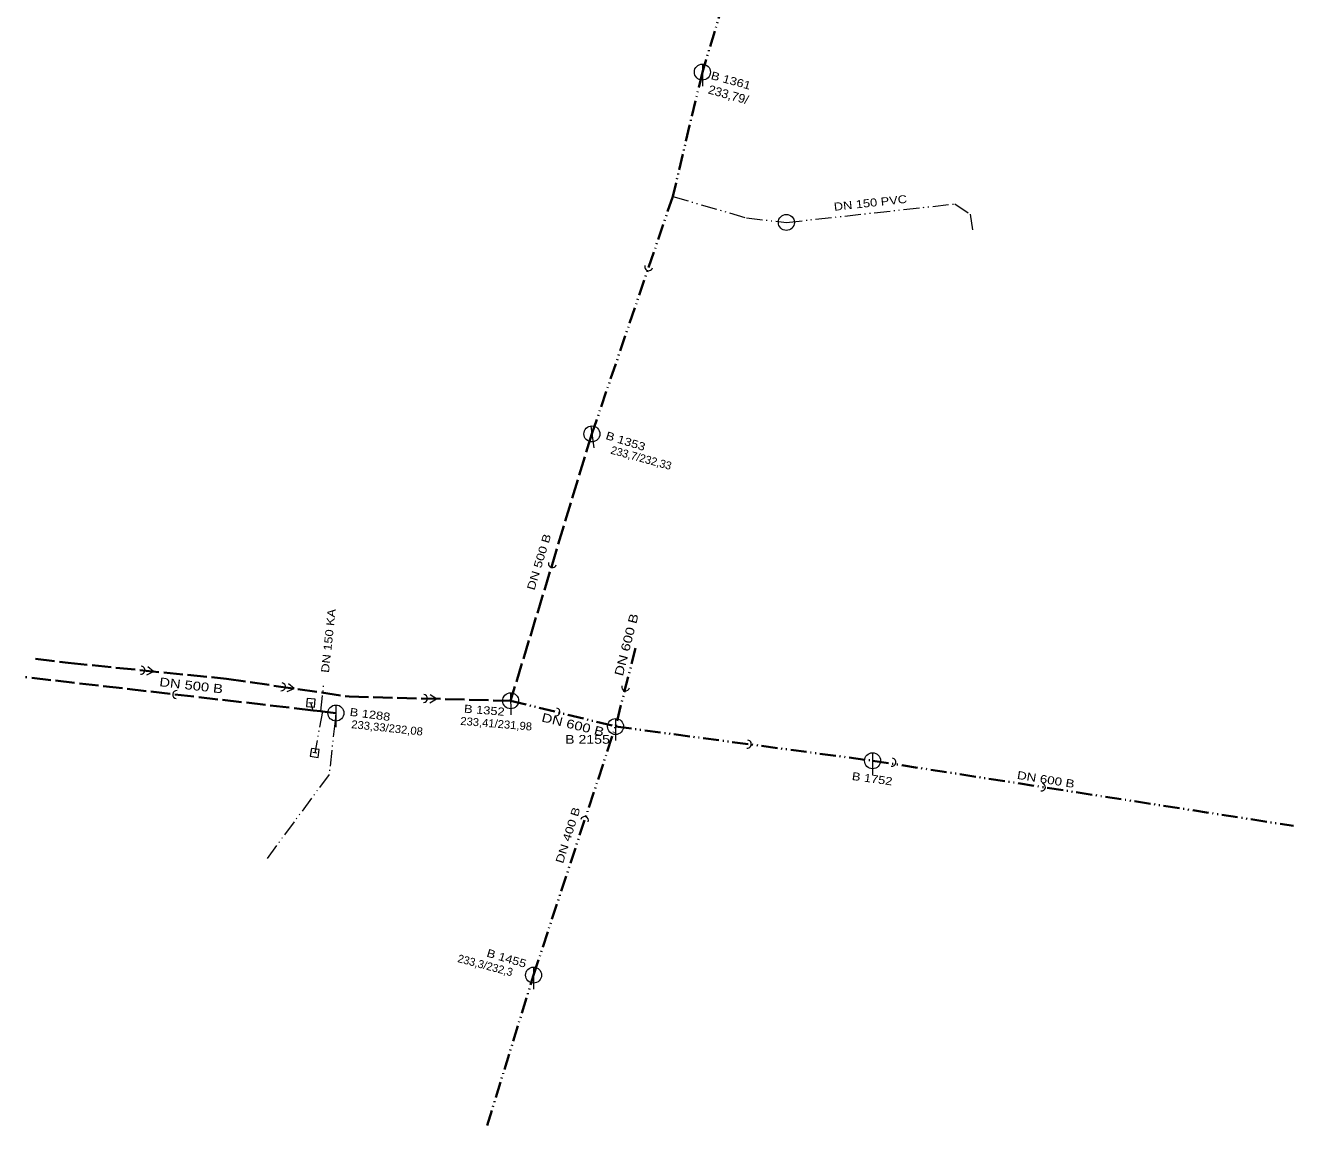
# Model space of a CAD drawing. Extents: x -645297 to -645138, y -1043752 to -1043474.
# Drawn here: x -645296.8 to -645138.3, y -1043751.8 to -1043614.2 of the extents above; entities that cross this region are included whole.
import ezdxf
from ezdxf.enums import TextEntityAlignment as Align

# ---------------------------------------------------------------- set-up
doc = ezdxf.new("R2010")
doc.units = 0
doc.header["$LTSCALE"] = 0.4
doc.linetypes.add('DASH_DOUBLE_DOT', pattern=[9.2, 5, -1.2, 0.3, -1.2, 0.3, -1.2])
doc.linetypes.add('LONG_DASHED', pattern=[7.5, 6, -1.5])
for name, color, linetype, lineweight in [('10', 7, 'Continuous', 13), ('14', 7, 'Continuous', 13), ('23', 7, 'LONG_DASHED', 35), ('24', 7, 'DASH_DOUBLE_DOT', 35), ('26', 7, 'DASH_DOUBLE_DOT', 35), ('34', 7, 'DASH_DOUBLE_DOT', 13), ('36', 7, 'DASH_DOUBLE_DOT', 13)]:
    doc.layers.add(name, color=color, linetype=linetype, lineweight=lineweight)
doc.layers.add('29', color=7, linetype='Continuous')
doc.layers.add('39', color=7, linetype='Continuous')

msp = doc.modelspace()

# ---------------------------------------------------------------- linework, layer by layer
at = {"layer": '10'}
for p, q in [((-645212.225, -1043619.066), (-645212.225, -1043621.814)), ((-645226.159, -1043664.308), (-645225.805, -1043667.033)), ((-645260.911, -1043698.942), (-645261.409, -1043698.898)), ((-645236.186, -1043697.65), (-645236.17, -1043700.398)), ((-645258.01, -1043699.18), (-645258.01, -1043701.928)), ((-645223.075, -1043700.865), (-645223.075, -1043703.613)), ((-645260.402, -1043705.192), (-645260.898, -1043705.128)), ((-645190.957, -1043705.14), (-645190.964, -1043707.888)), ((-645233.32, -1043731.94), (-645233.32, -1043734.688))]:
    msp.add_line(p, q, dxfattribs=at)
for points in [[(-645260.618, -1043698.466), (-645261.614, -1043698.378), (-645261.702, -1043699.374), (-645260.706, -1043699.462)], [(-645260.09, -1043704.729), (-645261.081, -1043704.6), (-645261.21, -1043705.591), (-645260.219, -1043705.72)]]:
    msp.add_lwpolyline(points, close=True, dxfattribs=at)
for centre, radius in [((-645212.2247, -1043620.0663), 1.0002), ((-645201.7333, -1043638.8638), 1), ((-645226.0301, -1043665.3002), 1.0002), ((-645236.1801, -1043698.6502), 1.0002), ((-645258.0097, -1043700.1803), 1.0002), ((-645223.0747, -1043701.8653), 1.0002), ((-645190.9597, -1043706.1403), 1.0002), ((-645233.3197, -1043732.9403), 1.0002)]:
    msp.add_circle(centre, radius, dxfattribs=at)
at = {"layer": '14'}
for points in [[(-645281.631, -1043695.407), (-645280.785, -1043694.99), (-645281.531, -1043694.412)], [(-645264.088, -1043697.51), (-645263.224, -1043697.13), (-645263.944, -1043696.52)], [(-645246.274, -1043698.89), (-645245.461, -1043698.411), (-645246.248, -1043697.89)]]:
    msp.add_lwpolyline(points, dxfattribs=at)
for centre, start, end in [((-645218.9241, -1043644.393), 163.02829, 343.02829), ((-645230.9599, -1043681.4969), 163.07249, 343.07249), ((-645282.3763, -1043694.8297), 264.28367, 84.28367), ((-645277.9037, -1043697.877), 83.39779, 263.39779), ((-645264.8069, -1043696.8994), 261.73408, 81.73408), ((-645221.8048, -1043696.9106), 165.61424, 345.61424), ((-645247.06, -1043698.3688), 268.52246, 88.52246), ((-645230.5152, -1043700.0405), 256.21607, 76.21607), ((-645206.6052, -1043704.0577), 262.41763, 82.41763), ((-645188.5448, -1043706.3294), 260.84248, 80.84248), ((-645169.8615, -1043709.4306), 261.13659, 81.13659), ((-645226.9519, -1043713.6266), 341.75332, 161.75332)]:
    msp.add_arc(centre, 0.5, start, end, dxfattribs=at)
at = {"layer": '23'}
for p, q in [((-645226.03, -1043665.3), (-645236.18, -1043698.65)), ((-645260.853, -1043699.851), (-645296.813, -1043695.689)), ((-645258.01, -1043700.18), (-645259.701, -1043699.984))]:
    msp.add_line(p, q, dxfattribs=at)
for points in [[(-645295.547, -1043693.425), (-645291.47, -1043693.92), (-645271.69, -1043695.9), (-645256.34, -1043698.13), (-645236.18, -1043698.65)], [(-645259.89, -1043699.962), (-645260.853, -1043699.851), (-645260.853, -1043699.851)], [(-645259.701, -1043699.984), (-645259.89, -1043699.962), (-645259.89, -1043699.962)]]:
    msp.add_lwpolyline(points, dxfattribs=at)
at = {"layer": '24'}
for p, q in [((-645215.918, -1043635.618), (-645226.03, -1043665.3)), ((-645236.18, -1043698.65), (-645223.075, -1043701.865)), ((-645233.32, -1043732.94), (-645223.075, -1043701.865)), ((-645190.96, -1043706.14), (-645138.35, -1043714.29)), ((-645239.123, -1043751.752), (-645233.32, -1043732.94))]:
    msp.add_line(p, q, dxfattribs=at)
for points in [[(-645209.622, -1043611.451), (-645212.225, -1043620.066), (-645213.814, -1043626.756), (-645215.918, -1043635.618)], [(-645223.075, -1043701.865), (-645190.96, -1043706.14), (-645190.96, -1043706.14)]]:
    msp.add_lwpolyline(points, dxfattribs=at)
at = {"layer": '26'}
msp.add_line((-645220.566, -1043692.083), (-645223.075, -1043701.865), dxfattribs=at)
at = {"layer": '34'}
for p, q in [((-645259.89, -1043699.962), (-645259.52, -1043696.547)), ((-645258.01, -1043700.18), (-645258.121, -1043701.174))]:
    msp.add_line(p, q, dxfattribs=at)
for points in [[(-645215.918, -1043635.618), (-645206.707, -1043638.296), (-645201.733, -1043638.864), (-645201.733, -1043638.864)], [(-645201.733, -1043638.864), (-645180.674, -1043636.548), (-645178.757, -1043637.821), (-645178.412, -1043640.144)], [(-645258.121, -1043701.174), (-645258.866, -1043707.872), (-645266.667, -1043718.418)]]:
    msp.add_lwpolyline(points, dxfattribs=at)
at = {"layer": '36'}
for p, q in [((-645260.853, -1043699.851), (-645261.16, -1043698.92)), ((-645259.701, -1043699.984), (-645260.65, -1043705.16))]:
    msp.add_line(p, q, dxfattribs=at)

# ---------------------------------------------------------------- texts
at = {"layer": '29', "width": 1.2}
for s, rotation, p in [('B 1361', 344.577, (-645211.236, -1043620.927)), ('B 1353', 342.647, (-645224.387, -1043665.92)), ('B 1288', 352.6, (-645256.328, -1043700.52)), ('B 1352', 355.384, (-645242.037, -1043700.121)), ('B 1752', 352.121, (-645193.59, -1043708.538)), ('B 1455', 343.545, (-645239.26, -1043730.598))]:
    msp.add_text(s, height=1, rotation=rotation, dxfattribs=at).set_placement(p)
at = {"layer": '29'}
for s, height, rotation, width, p in [('233,79/', 1.1, 344.225, 1.05, (-645209.113, -1043623.4174)), ('DN 500 B', 1, 73.072, 1.25, (-645232.1615, -1043681.4426)), ('DN 600 B', 1.1, 75.614, 1.25, (-645221.1764, -1043691.7766)), ('DN 500 B', 1.1, 353.399, 1.25, (-645276.1522, -1043697.2728)), ('233,41/231,98', 1, 355.408, 1.05, (-645238.025, -1043702.0133)), ('DN 600 B', 1.1, 346.216, 1.25, (-645228.523, -1043702.1644)), ('233,33/232,08', 1, 353.976, 1.05, (-645251.666, -1043702.5331)), ('DN 600 B', 1, 350.843, 1.25, (-645169.3876, -1043708.9769)), ('DN 400 B', 1, 72.472, 1.25, (-645228.5526, -1043715.6006))]:
    msp.add_text(s, height=height, rotation=rotation, dxfattribs=dict(at, width=width)).set_placement(p, align=Align.CENTER)
for s, rotation, p in [('233,7/232,33', 344.685, (-645220.0011, -1043668.7766)), ('233,3/232,3', 345.138, (-645239.4757, -1043732.1923))]:
    msp.add_text(s, height=1, rotation=rotation, dxfattribs=at).set_placement(p, align=Align.CENTER)
at = {"layer": '29', "width": 1.2}
msp.add_text('B 2155', height=1.1, dxfattribs=at).set_placement((-645226.577, -1043704.022), align=Align.CENTER)
at = {"layer": '39', "width": 1.2}
for s, rotation, p in [('DN 150 PVC', 6.276, (-645191.1767, -1043636.9093)), ('DN 150 KA', 83.816, (-645258.454, -1043691.1979))]:
    msp.add_text(s, height=1, rotation=rotation, dxfattribs=at).set_placement(p, align=Align.CENTER)

doc.saveas('drawing.dxf')
